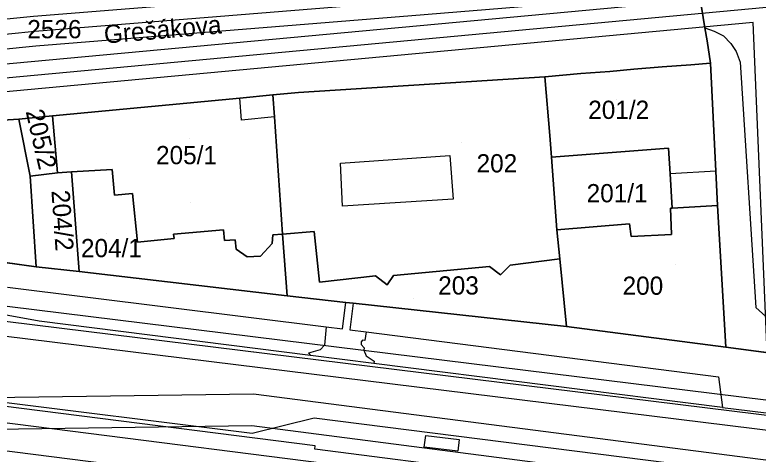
# Model space of a CAD drawing. Extents: x -263423 to -261326, y -1240067 to -1237864.
# Drawn here: x -263115.3 to -263033.7, y -1240015.3 to -1239967.1 of the extents above; entities that cross this region are included whole.
import ezdxf

# ---------------------------------------------------------------- set-up
doc = ezdxf.new("R2010")
doc.units = 0
for name, color, linetype in [('body_kn', 7, 'Continuous'), ('kladpar_druhypozemkov', 7, 'Continuous'), ('kladpar_hranice', 7, 'Continuous'), ('kladpar_parcelnecisla', 7, 'Continuous'), ('kladpar_plochy', 7, 'Continuous'), ('linie', 7, 'Continuous'), ('popisy', 7, 'Continuous'), ('tarchy_linie', 7, 'Continuous'), ('zappar_hrandruhpozemk', 7, 'Continuous'), ('znacky', 7, 'Continuous')]:
    doc.layers.add(name, color=color, linetype=linetype)

msp = doc.modelspace()

# ---------------------------------------------------------------- linework, layer by layer
at = {"layer": 'body_kn'}
for p, q in [((-263113.26, -1239967.22), (-263113.26, -1239967.22)), ((-263071.74, -1239967.17), (-263071.74, -1239967.17)), ((-263039.54, -1239968.47), (-263039.54, -1239968.47)), ((-263039.54, -1239968.47), (-263039.54, -1239968.47)), ((-263034.24, -1239967.9), (-263034.24, -1239967.9)), ((-263113.13, -1239968.86), (-263113.13, -1239968.86)), ((-263038.53, -1239968.85), (-263038.53, -1239968.85)), ((-263037.51, -1239969.37), (-263037.51, -1239969.37)), ((-263039.3, -1239969.93), (-263039.3, -1239969.93)), ((-263036.68, -1239970.2), (-263036.68, -1239970.2)), ((-263113, -1239970.5), (-263113, -1239970.5)), ((-263036.11, -1239971.1), (-263036.11, -1239971.1)), ((-263041.09, -1239972.54), (-263041.09, -1239972.54)), ((-263038.92, -1239972.36), (-263038.92, -1239972.36)), ((-263035.67, -1239972.24), (-263035.67, -1239972.24)), ((-263049.97, -1239973.26), (-263049.97, -1239973.26)), ((-263047.35, -1239973.02), (-263047.35, -1239973.02)), ((-263044.22, -1239972.78), (-263044.22, -1239972.78)), ((-263057.11, -1239973.87), (-263057.11, -1239973.87)), ((-263057.11, -1239973.87), (-263057.11, -1239973.87)), ((-263053.16, -1239973.5), (-263053.16, -1239973.5)), ((-263086.98, -1239975.83), (-263086.98, -1239975.83)), ((-263084.18, -1239975.59), (-263084.18, -1239975.59)), ((-263090.62, -1239976.19), (-263090.62, -1239976.19)), ((-263090.62, -1239976.19), (-263090.62, -1239976.19)), ((-263111.18, -1239978.14), (-263111.18, -1239978.14)), ((-263111.18, -1239978.14), (-263111.18, -1239978.14)), ((-263086.81, -1239978.25), (-263086.81, -1239978.25)), ((-263086.81, -1239978.25), (-263086.81, -1239978.25)), ((-263114.88, -1239978.5), (-263114.88, -1239978.5)), ((-263114.88, -1239978.5), (-263114.88, -1239978.5)), ((-263090.44, -1239978.62), (-263090.44, -1239978.62)), ((-263056.57, -1239980.31), (-263056.57, -1239980.31)), ((-263043.52, -1239981.68), (-263043.52, -1239981.68)), ((-263067.55, -1239982.49), (-263067.55, -1239982.49)), ((-263056.39, -1239982.67), (-263056.39, -1239982.67)), ((-263104.63, -1239984.03), (-263104.63, -1239984.03)), ((-263079.55, -1239983.32), (-263079.55, -1239983.32)), ((-263079.55, -1239983.32), (-263079.55, -1239983.32)), ((-263113.64, -1239984.76), (-263113.64, -1239984.76)), ((-263110.64, -1239984.39), (-263110.64, -1239984.39)), ((-263110.64, -1239984.39), (-263110.64, -1239984.39)), ((-263109.1, -1239984.27), (-263109.1, -1239984.27)), ((-263043.35, -1239984.52), (-263043.35, -1239984.52)), ((-263038.35, -1239984.2), (-263038.35, -1239984.2)), ((-263038.35, -1239984.2), (-263038.35, -1239984.2)), ((-263104.39, -1239986.84), (-263104.39, -1239986.84)), ((-263102.41, -1239986.66), (-263102.41, -1239986.66)), ((-263067.19, -1239987.27), (-263067.19, -1239987.27)), ((-263079.32, -1239988.04), (-263079.32, -1239988.04)), ((-263038.17, -1239987.98), (-263038.17, -1239987.98)), ((-263043.33, -1239988.28), (-263043.33, -1239988.28)), ((-263043.12, -1239988.27), (-263043.12, -1239988.27)), ((-263043.12, -1239988.27), (-263043.12, -1239988.27)), ((-263047.81, -1239989.98), (-263047.81, -1239989.98)), ((-263097.9, -1239991.14), (-263097.9, -1239991.14)), ((-263092.41, -1239990.66), (-263092.41, -1239990.66)), ((-263086.99, -1239991.2), (-263086.99, -1239991.2)), ((-263085.91, -1239991.14), (-263085.91, -1239991.14)), ((-263082.46, -1239990.83), (-263082.46, -1239990.83)), ((-263055.79, -1239990.64), (-263055.79, -1239990.64)), ((-263047.62, -1239991.38), (-263047.62, -1239991.38)), ((-263043.22, -1239991.15), (-263043.22, -1239991.15)), ((-263043.22, -1239991.15), (-263043.22, -1239991.15)), ((-263101.86, -1239992.02), (-263101.86, -1239992.02)), ((-263097.84, -1239991.59), (-263097.84, -1239991.59)), ((-263097.84, -1239991.59), (-263097.84, -1239991.59)), ((-263092.29, -1239991.81), (-263092.29, -1239991.81)), ((-263091.14, -1239991.75), (-263091.14, -1239991.75)), ((-263087.06, -1239992.15), (-263087.06, -1239992.15)), ((-263091.02, -1239992.77), (-263091.02, -1239992.77)), ((-263089.81, -1239993.6), (-263089.81, -1239993.6)), ((-263088.34, -1239993.55), (-263088.34, -1239993.55)), ((-263055.48, -1239993.83), (-263055.48, -1239993.83)), ((-263063.21, -1239994.69), (-263063.21, -1239994.69)), ((-263063.21, -1239994.69), (-263063.21, -1239994.69)), ((-263060.91, -1239994.51), (-263060.91, -1239994.51)), ((-263112.98, -1239994.71), (-263112.98, -1239994.71)), ((-263108.26, -1239995.24), (-263108.26, -1239995.24)), ((-263075.72, -1239995.71), (-263075.72, -1239995.71)), ((-263073.74, -1239995.66), (-263073.74, -1239995.66)), ((-263062, -1239995.58), (-263062, -1239995.58)), ((-263081.85, -1239996.38), (-263081.85, -1239996.38)), ((-263074.45, -1239996.67), (-263074.45, -1239996.67)), ((-263085.43, -1239997.9), (-263085.43, -1239997.9)), ((-263078.96, -1239998.61), (-263078.96, -1239998.61)), ((-263078.18, -1239998.7), (-263078.18, -1239998.7)), ((-263078.18, -1239998.7), (-263078.18, -1239998.7)), ((-263033.93, -1239999.16), (-263033.93, -1239999.16)), ((-263033.93, -1239999.16), (-263033.93, -1239999.16)), ((-263112.66, -1240000.67), (-263112.66, -1240000.67)), ((-263081.12, -1240001.29), (-263081.12, -1240001.29)), ((-263079.35, -1240001.53), (-263079.35, -1240001.53)), ((-263078.54, -1240001.63), (-263078.54, -1240001.63)), ((-263076.72, -1240001.83), (-263076.72, -1240001.83)), ((-263076.72, -1240001.83), (-263076.72, -1240001.83)), ((-263054.74, -1240001.27), (-263054.74, -1240001.27)), ((-263077.13, -1240002.77), (-263077.13, -1240002.77)), ((-263076.89, -1240002.81), (-263076.89, -1240002.81)), ((-263081.33, -1240003.29), (-263081.33, -1240003.29)), ((-263077.27, -1240002.94), (-263077.27, -1240002.94)), ((-263077.27, -1240003.25), (-263077.27, -1240003.25)), ((-263076.97, -1240003.58), (-263076.97, -1240003.58)), ((-263037.25, -1240003.54), (-263037.25, -1240003.54)), ((-263083.06, -1240004.17), (-263083.06, -1240004.17)), ((-263082.84, -1240004.45), (-263082.84, -1240004.45)), ((-263082.84, -1240004.45), (-263082.84, -1240004.45)), ((-263081.8, -1240003.83), (-263081.8, -1240003.83)), ((-263077, -1240003.87), (-263077, -1240003.87)), ((-263076.72, -1240004.49), (-263076.72, -1240004.49)), ((-263075.9, -1240005.31), (-263075.9, -1240005.31)), ((-263075.9, -1240005.31), (-263075.9, -1240005.31)), ((-263075.86, -1240005.06), (-263075.86, -1240005.06)), ((-263038.05, -1240006.77), (-263038.05, -1240006.77)), ((-263089.1, -1240008.68), (-263089.1, -1240008.68)), ((-263037.59, -1240010.14), (-263037.59, -1240010.14)), ((-263082.45, -1240011.29), (-263082.45, -1240011.29)), ((-263089.3, -1240012.13), (-263089.3, -1240012.13)), ((-263089.25, -1240012.96), (-263089.25, -1240012.96)), ((-263070.2, -1240013.2), (-263070.2, -1240013.2)), ((-263070.2, -1240013.2), (-263070.2, -1240013.2)), ((-263066.54, -1240013.65), (-263066.54, -1240013.65)), ((-263082.37, -1240014.72), (-263082.37, -1240014.72)), ((-263082.32, -1240014.35), (-263082.32, -1240014.35)), ((-263070.36, -1240014.49), (-263070.36, -1240014.49)), ((-263066.69, -1240014.94), (-263066.69, -1240014.94))]:
    msp.add_line(p, q, dxfattribs=at)
at = {"layer": 'kladpar_druhypozemkov'}
for p, q in [((-263109.99, -1239968), (-263109.99, -1239968)), ((-263049.23, -1239976.3), (-263049.23, -1239976.3)), ((-263096.11, -1239980.65), (-263096.11, -1239980.65)), ((-263062.41, -1239982.25), (-263062.41, -1239982.25)), ((-263111.43, -1239982.58), (-263111.43, -1239982.58)), ((-263049.51, -1239985.99), (-263049.51, -1239985.99)), ((-263110.81, -1239986.67), (-263110.81, -1239986.67)), ((-263105.21, -1239991.05), (-263105.21, -1239991.05)), ((-263046.23, -1239995.48), (-263046.23, -1239995.48)), ((-263071.56, -1239998.13), (-263071.56, -1239998.13))]:
    msp.add_line(p, q, dxfattribs=at)
at = {"layer": 'kladpar_hranice'}
for points in [[(-263041.28, -1239957.81), (-263039.54, -1239968.47), (-263039.3, -1239969.93), (-263038.92, -1239972.36), (-263041.09, -1239972.54), (-263044.22, -1239972.78), (-263047.35, -1239973.02), (-263049.97, -1239973.26), (-263053.16, -1239973.5), (-263057.11, -1239973.87), (-263084.18, -1239975.59), (-263086.98, -1239975.83), (-263090.62, -1239976.19), (-263111.18, -1239978.14), (-263114.88, -1239978.5), (-263126.49, -1239979.23), (-263141.92, -1239980.45), (-263141.92, -1239978.54), (-263141.99, -1239976.76), (-263142.19, -1239966.77)], [(-263027.8, -1240004.77), (-263037.25, -1240003.54), (-263038.17, -1239987.98), (-263038.35, -1239984.2), (-263038.92, -1239972.36), (-263039.3, -1239969.93), (-263039.54, -1239968.47), (-263041.28, -1239957.81)], [(-263057.11, -1239973.87), (-263053.16, -1239973.5), (-263049.97, -1239973.26), (-263047.35, -1239973.02), (-263044.22, -1239972.78), (-263041.09, -1239972.54), (-263038.92, -1239972.36), (-263038.35, -1239984.2), (-263038.17, -1239987.98), (-263043.12, -1239988.27), (-263043.35, -1239984.52), (-263043.52, -1239981.68), (-263056.39, -1239982.67), (-263056.57, -1239980.31), (-263057.11, -1239973.87)], [(-263057.11, -1239973.87), (-263056.57, -1239980.31), (-263056.39, -1239982.67), (-263055.79, -1239990.64), (-263055.48, -1239993.83), (-263060.91, -1239994.51), (-263062, -1239995.58), (-263063.21, -1239994.69), (-263073.74, -1239995.66), (-263074.45, -1239996.67), (-263075.72, -1239995.71), (-263081.85, -1239996.38), (-263082.46, -1239990.83), (-263085.91, -1239991.14), (-263086.81, -1239978.25), (-263086.98, -1239975.83), (-263084.18, -1239975.59), (-263057.11, -1239973.87)], [(-263090.62, -1239976.19), (-263086.98, -1239975.83), (-263086.81, -1239978.25), (-263085.91, -1239991.14), (-263086.99, -1239991.2), (-263087.06, -1239992.15), (-263088.34, -1239993.55), (-263089.81, -1239993.6), (-263091.02, -1239992.77), (-263091.14, -1239991.75), (-263092.29, -1239991.81), (-263092.41, -1239990.66), (-263097.9, -1239991.14), (-263097.84, -1239991.59), (-263101.86, -1239992.02), (-263102.41, -1239986.66), (-263104.39, -1239986.84), (-263104.63, -1239984.03), (-263109.1, -1239984.27), (-263110.64, -1239984.39), (-263111.18, -1239978.14), (-263090.62, -1239976.19)], [(-263111.18, -1239978.14), (-263110.64, -1239984.39), (-263113.64, -1239984.76), (-263114.88, -1239978.5), (-263111.18, -1239978.14)], [(-263114.88, -1239978.5), (-263113.64, -1239984.76), (-263112.98, -1239994.71), (-263127.67, -1239992.66), (-263127.94, -1239985.22), (-263126.16, -1239985.22), (-263126.49, -1239979.23), (-263114.88, -1239978.5)], [(-263043.12, -1239988.27), (-263043.33, -1239988.28), (-263043.22, -1239991.15), (-263047.62, -1239991.38), (-263047.81, -1239989.98), (-263055.79, -1239990.64), (-263056.39, -1239982.67), (-263043.52, -1239981.68), (-263043.35, -1239984.52), (-263043.12, -1239988.27)], [(-263097.84, -1239991.59), (-263097.9, -1239991.14), (-263092.41, -1239990.66), (-263092.29, -1239991.81), (-263091.14, -1239991.75), (-263091.02, -1239992.77), (-263089.81, -1239993.6), (-263088.34, -1239993.55), (-263087.06, -1239992.15), (-263086.99, -1239991.2), (-263085.91, -1239991.14), (-263085.43, -1239997.9), (-263108.26, -1239995.24), (-263109.1, -1239984.27), (-263104.63, -1239984.03), (-263104.39, -1239986.84), (-263102.41, -1239986.66), (-263101.86, -1239992.02), (-263097.84, -1239991.59)], [(-263110.64, -1239984.39), (-263109.1, -1239984.27), (-263108.26, -1239995.24), (-263112.98, -1239994.71), (-263113.64, -1239984.76), (-263110.64, -1239984.39)], [(-263043.22, -1239991.15), (-263043.33, -1239988.28), (-263043.12, -1239988.27), (-263038.17, -1239987.98), (-263037.25, -1240003.54), (-263054.74, -1240001.27), (-263055.48, -1239993.83), (-263055.79, -1239990.64), (-263047.81, -1239989.98), (-263047.62, -1239991.38), (-263043.22, -1239991.15)], [(-263063.21, -1239994.69), (-263062, -1239995.58), (-263060.91, -1239994.51), (-263055.48, -1239993.83), (-263054.74, -1240001.27), (-263078.18, -1239998.7), (-263078.96, -1239998.61), (-263085.43, -1239997.9), (-263085.91, -1239991.14), (-263082.46, -1239990.83), (-263081.85, -1239996.38), (-263075.72, -1239995.71), (-263074.45, -1239996.67), (-263073.74, -1239995.66), (-263063.21, -1239994.69)], [(-263160.43, -1239993.94), (-263153.75, -1239994.6), (-263143.1, -1239995.66), (-263142.56, -1239994.94), (-263141.33, -1239993.32), (-263140.06, -1239991.65), (-263138.53, -1239991.84), (-263127.67, -1239992.66), (-263112.98, -1239994.71), (-263108.26, -1239995.24), (-263085.43, -1239997.9), (-263078.96, -1239998.61), (-263078.18, -1239998.7), (-263054.74, -1240001.27), (-263037.25, -1240003.54), (-263027.8, -1240004.77)]]:
    msp.add_lwpolyline(points, dxfattribs=at)
at = {"layer": 'kladpar_plochy'}
for p, q in [((-263127.67, -1239992.66), (-263112.98, -1239994.71)), ((-263112.98, -1239994.71), (-263108.26, -1239995.24)), ((-263108.26, -1239995.24), (-263085.43, -1239997.9)), ((-263085.43, -1239997.9), (-263078.96, -1239998.61)), ((-263078.96, -1239998.61), (-263078.18, -1239998.7)), ((-263078.18, -1239998.7), (-263054.74, -1240001.27)), ((-263054.74, -1240001.27), (-263037.25, -1240003.54)), ((-263037.25, -1240003.54), (-263027.8, -1240004.77))]:
    msp.add_line(p, q, dxfattribs=at)
for points in [[(-263041.28, -1239957.81), (-263039.54, -1239968.47), (-263039.3, -1239969.93), (-263038.92, -1239972.36), (-263041.09, -1239972.54), (-263044.22, -1239972.78), (-263047.35, -1239973.02), (-263049.97, -1239973.26), (-263053.16, -1239973.5), (-263057.11, -1239973.87), (-263084.18, -1239975.59), (-263086.98, -1239975.83), (-263090.62, -1239976.19), (-263111.18, -1239978.14), (-263114.88, -1239978.5), (-263126.49, -1239979.23), (-263141.92, -1239980.45), (-263141.92, -1239978.54), (-263141.99, -1239976.76), (-263142.19, -1239966.77)], [(-263027.8, -1240004.77), (-263037.25, -1240003.54), (-263038.17, -1239987.98), (-263038.35, -1239984.2), (-263038.92, -1239972.36), (-263039.3, -1239969.93), (-263039.54, -1239968.47), (-263041.28, -1239957.81)]]:
    msp.add_lwpolyline(points, dxfattribs=at)
for points in [[(-263057.11, -1239973.87), (-263053.16, -1239973.5), (-263049.97, -1239973.26), (-263047.35, -1239973.02), (-263044.22, -1239972.78), (-263041.09, -1239972.54), (-263038.92, -1239972.36), (-263038.35, -1239984.2), (-263038.17, -1239987.98), (-263043.12, -1239988.27), (-263043.35, -1239984.52), (-263043.52, -1239981.68), (-263056.39, -1239982.67), (-263056.57, -1239980.31)], [(-263057.11, -1239973.87), (-263056.57, -1239980.31), (-263056.39, -1239982.67), (-263055.79, -1239990.64), (-263055.48, -1239993.83), (-263060.91, -1239994.51), (-263062, -1239995.58), (-263063.21, -1239994.69), (-263073.74, -1239995.66), (-263074.45, -1239996.67), (-263075.72, -1239995.71), (-263081.85, -1239996.38), (-263082.46, -1239990.83), (-263085.91, -1239991.14), (-263086.81, -1239978.25), (-263086.98, -1239975.83), (-263084.18, -1239975.59)], [(-263090.62, -1239976.19), (-263086.98, -1239975.83), (-263086.81, -1239978.25), (-263085.91, -1239991.14), (-263086.99, -1239991.2), (-263087.06, -1239992.15), (-263088.34, -1239993.55), (-263089.81, -1239993.6), (-263091.02, -1239992.77), (-263091.14, -1239991.75), (-263092.29, -1239991.81), (-263092.41, -1239990.66), (-263097.9, -1239991.14), (-263097.84, -1239991.59), (-263101.86, -1239992.02), (-263102.41, -1239986.66), (-263104.39, -1239986.84), (-263104.63, -1239984.03), (-263109.1, -1239984.27), (-263110.64, -1239984.39), (-263111.18, -1239978.14)], [(-263111.18, -1239978.14), (-263110.64, -1239984.39), (-263113.64, -1239984.76), (-263114.88, -1239978.5)], [(-263114.88, -1239978.5), (-263113.64, -1239984.76), (-263112.98, -1239994.71), (-263127.67, -1239992.66), (-263127.94, -1239985.22), (-263126.16, -1239985.22), (-263126.49, -1239979.23)], [(-263043.12, -1239988.27), (-263043.33, -1239988.28), (-263043.22, -1239991.15), (-263047.62, -1239991.38), (-263047.81, -1239989.98), (-263055.79, -1239990.64), (-263056.39, -1239982.67), (-263043.52, -1239981.68), (-263043.35, -1239984.52)], [(-263097.84, -1239991.59), (-263097.9, -1239991.14), (-263092.41, -1239990.66), (-263092.29, -1239991.81), (-263091.14, -1239991.75), (-263091.02, -1239992.77), (-263089.81, -1239993.6), (-263088.34, -1239993.55), (-263087.06, -1239992.15), (-263086.99, -1239991.2), (-263085.91, -1239991.14), (-263085.43, -1239997.9), (-263108.26, -1239995.24), (-263109.1, -1239984.27), (-263104.63, -1239984.03), (-263104.39, -1239986.84), (-263102.41, -1239986.66), (-263101.86, -1239992.02)], [(-263110.64, -1239984.39), (-263109.1, -1239984.27), (-263108.26, -1239995.24), (-263112.98, -1239994.71), (-263113.64, -1239984.76)], [(-263043.22, -1239991.15), (-263043.33, -1239988.28), (-263043.12, -1239988.27), (-263038.17, -1239987.98), (-263037.25, -1240003.54), (-263054.74, -1240001.27), (-263055.48, -1239993.83), (-263055.79, -1239990.64), (-263047.81, -1239989.98), (-263047.62, -1239991.38)], [(-263063.21, -1239994.69), (-263062, -1239995.58), (-263060.91, -1239994.51), (-263055.48, -1239993.83), (-263054.74, -1240001.27), (-263078.18, -1239998.7), (-263078.96, -1239998.61), (-263085.43, -1239997.9), (-263085.91, -1239991.14), (-263082.46, -1239990.83), (-263081.85, -1239996.38), (-263075.72, -1239995.71), (-263074.45, -1239996.67), (-263073.74, -1239995.66)]]:
    msp.add_lwpolyline(points, close=True, dxfattribs=at)
at = {"layer": 'linie'}
for points in [[(-263294.31, -1239988.67), (-263268.78, -1239991.92), (-263241.89, -1239995.4), (-263207.05, -1240000.27), (-262981.57, -1240028.93)], [(-262975.3, -1240032.85), (-263221.73, -1240001.53), (-263271.17, -1239995.24), (-263294.25, -1239992.31)]]:
    msp.add_lwpolyline(points, dxfattribs=at)
at = {"layer": 'tarchy_linie'}
for points in [[(-263032.71, -1240004.13), (-263034.24, -1239967.9), (-263141.95, -1239977.89), (-263141.99, -1239976.76), (-263142, -1239976.35), (-263142.03, -1239974.81), (-263034.41, -1239964.83), (-263034.46, -1239964.1), (-263071.74, -1239967.17), (-263113, -1239970.5), (-263142.06, -1239973.41), (-263142.09, -1239971.76), (-263142.12, -1239970.1), (-263113.26, -1239967.22), (-263072.02, -1239963.89), (-263034.7, -1239960.81), (-263041.94, -1239858.97), (-263043.84, -1239830.4), (-263079.55, -1239832.65), (-263160.09, -1239838.14), (-263160.09, -1239836.48), (-263160.1, -1239834.82), (-263079.77, -1239829.35)], [(-263142.09, -1239971.76), (-263113.13, -1239968.86), (-263071.88, -1239965.53), (-263029.83, -1239962.06), (-262987.48, -1239958.22), (-262956.48, -1239955.32), (-262944.89, -1239954.43), (-262902.79, -1239950.4), (-262859.08, -1239946.41), (-262815.45, -1239942.96)], [(-263142, -1239976.35), (-263032.77, -1239966.22), (-262901.51, -1239953.72), (-262809.55, -1239945.43)], [(-263190.37, -1239978.1), (-263157.01, -1239977.05), (-263157.34, -1239973.44), (-263159.9, -1239950.26), (-263157.06, -1239950.07), (-263152.42, -1239949.77), (-263150.78, -1239949.66), (-263149.14, -1239970.88), (-263142.12, -1239970.1), (-263142.09, -1239971.76), (-263142.06, -1239973.41), (-263148.89, -1239974.17), (-263148.78, -1239975.59), (-263142.03, -1239974.81), (-263142, -1239976.35), (-263141.99, -1239976.76), (-263141.95, -1239977.89), (-263148.45, -1239978.65), (-263146.13, -1239993.5), (-263145.84, -1239995.36), (-263032.56, -1240009.33)], [(-263147.28, -1239996.85), (-263030.94, -1240011.19), (-262952.34, -1240022.76), (-262895.18, -1240015.48), (-262788.72, -1240005.88), (-262678.82, -1239972.02)], [(-263294.33, -1239987.55), (-263230.04, -1239998.95), (-263150.79, -1240013.01), (-263089.3, -1240012.13), (-263026.76, -1240020.2), (-262979.54, -1240026.3), (-262896.92, -1240020.74), (-262789.71, -1240011.94), (-262677.55, -1239975.98)], [(-262979.44, -1240022.84), (-263026.32, -1240016.78), (-263089.1, -1240008.68), (-263144.17, -1240009.46), (-263145.37, -1239998.75), (-263031.14, -1240012.83), (-262968.28, -1240022.08), (-262979.44, -1240022.84)]]:
    msp.add_lwpolyline(points, dxfattribs=at)
at = {"layer": 'zappar_hrandruhpozemk'}
for p, q in [((-263035.67, -1239972.24), (-263033.93, -1239999.16)), ((-263090.44, -1239978.62), (-263090.62, -1239976.19)), ((-263086.81, -1239978.25), (-263090.44, -1239978.62)), ((-263079.32, -1239988.04), (-263079.55, -1239983.32)), ((-263038.35, -1239984.2), (-263043.35, -1239984.52)), ((-263067.19, -1239987.27), (-263079.32, -1239988.04)), ((-263116.11, -1239996.95), (-263081.12, -1240001.29)), ((-263033.93, -1239999.16), (-263027.8, -1240004.77)), ((-263112.66, -1240000.67), (-263116.45, -1239999.98)), ((-263082.84, -1240004.45), (-263112.66, -1240000.67)), ((-263076.72, -1240001.83), (-263038.05, -1240006.77)), ((-263075.9, -1240005.31), (-263082.84, -1240004.45)), ((-263037.59, -1240010.14), (-263075.9, -1240005.31)), ((-263038.05, -1240006.77), (-263037.59, -1240010.14)), ((-263082.45, -1240011.29), (-263005.63, -1240020.97)), ((-263070.36, -1240014.49), (-263070.2, -1240013.2)), ((-263006.05, -1240024.43), (-263082.37, -1240014.72)), ((-263066.69, -1240014.94), (-263070.36, -1240014.49))]:
    msp.add_line(p, q, dxfattribs=at)
for points in [[(-263039.54, -1239968.47), (-263038.53, -1239968.85), (-263037.51, -1239969.37), (-263036.68, -1239970.2), (-263036.11, -1239971.1), (-263035.67, -1239972.24)], [(-263079.55, -1239983.32), (-263067.55, -1239982.49), (-263067.19, -1239987.27)], [(-263081.12, -1240001.29), (-263079.35, -1240001.53), (-263078.96, -1239998.61)], [(-263078.18, -1239998.7), (-263078.54, -1240001.63), (-263076.72, -1240001.83), (-263076.89, -1240002.81), (-263077.13, -1240002.77), (-263077.27, -1240002.94), (-263077.27, -1240003.25), (-263076.97, -1240003.58), (-263077, -1240003.87), (-263076.72, -1240004.49), (-263075.86, -1240005.06), (-263075.9, -1240005.31)], [(-263081.12, -1240001.29), (-263081.33, -1240003.29), (-263081.8, -1240003.83), (-263083.06, -1240004.17), (-263082.84, -1240004.45)], [(-263037.59, -1240010.14), (-263026.52, -1240011.5), (-263026.01, -1240011.18), (-263025.63, -1240010.86), (-263025.5, -1240010.36), (-263025.63, -1240009.66), (-263027.03, -1240005.34), (-263027.8, -1240004.77)], [(-263077.59, -1240026.81), (-263114.55, -1240020.62), (-263119.69, -1240019.68), (-263122.55, -1240018.66), (-263124.94, -1240017.52), (-263127.02, -1240016.34), (-263129.18, -1240014.83), (-263129.67, -1240014.34), (-263129.86, -1240013.86), (-263129.73, -1240013.53), (-263129.36, -1240012.95), (-263128.92, -1240012.5), (-263128.46, -1240012.15), (-263124.16, -1240009.59), (-263123.22, -1240009.26), (-263121.65, -1240008.91), (-263119.19, -1240009.22), (-263089.25, -1240012.96), (-263082.45, -1240011.29)], [(-263082.37, -1240014.72), (-263082.32, -1240014.35), (-263118.93, -1240009.71), (-263119.18, -1240009.46), (-263119.19, -1240009.22)], [(-263070.2, -1240013.2), (-263066.54, -1240013.65), (-263066.69, -1240014.94)]]:
    msp.add_lwpolyline(points, dxfattribs=at)
at = {"layer": 'znacky'}
for p, q in [((-263066.32, -1239981.02), (-263066.32, -1239981.02)), ((-263096.06, -1239987.61), (-263096.06, -1239987.61)), ((-263042.77, -1239994.4), (-263042.77, -1239994.4))]:
    msp.add_line(p, q, dxfattribs=at)

# ---------------------------------------------------------------- texts
at = {"layer": 'kladpar_parcelnecisla'}
for s, p in [('2526', (-263113.948, -1239969.63)), ('201/2', (-263052.354, -1239978.48)), ('205/1', (-263099.813, -1239983.45)), ('202', (-263064.614, -1239984.35)), ('201/1', (-263052.528, -1239987.63)), ('204/1', (-263108.058, -1239993.65)), ('203', (-263068.83, -1239997.75)), ('200', (-263048.579, -1239997.78))]:
    msp.add_text(s, height=2, dxfattribs=at).set_placement(p)
for s, rotation, p in [('205/2', 283, (-263114.141, -1239977.656)), ('204/2', 274, (-263111.304, -1239986.356))]:
    msp.add_text(s, height=2, rotation=rotation, dxfattribs=at).set_placement(p)
at = {"layer": 'popisy'}
msp.add_text('Grešákova', height=2, rotation=5, dxfattribs=at).set_placement((-263105.442, -1239970.224))

doc.saveas('drawing.dxf')
